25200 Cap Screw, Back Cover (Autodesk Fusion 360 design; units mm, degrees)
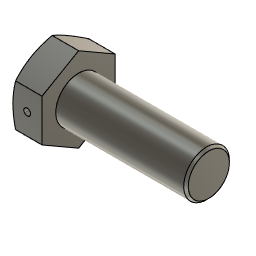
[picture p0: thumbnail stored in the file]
sketch "Main Profile" plane through (0, 0, 0) normal (0, 1, 0) x axis (1, 0, 0)
  line L1 (27.7812, 0) -> (0, 0)
  line L2 (27.7812, -3.9688) -> (27.7812, 0)
  line L3 (5.1594, -3.9687) -> (27.7812, -3.9688)
  line L4 (5.1594, -6.35) -> (5.1594, -3.9687)
  line L5 (0, -6.35) -> (5.1594, -6.35)
  line L6 (0, 0) -> (0, -6.35)
  point P1 (0, 0)
  point P2 (0, 0)
  point P8 (0, 0)
  point P4 (27.7812, -3.9688)
  point P5 (5.1594, -3.9687)
  point P6 (5.1594, -6.35)
  point P7 (0, -6.35)
  point P3 (27.7812, 0)
  coincident P1 P2
  horizontal L1
  perpendicular L1 L2
  perpendicular L2 L3
  perpendicular L3 L4
  perpendicular L4 L5
  coincident P1 P8
  vertical L6
  dimension "d1" distance P4 P5 = 22.6219
  dimension "d2" distance P6 P7 = 5.1594 (= "( 13 / 64 ) * 1 in")
  dimension "d3" distance P3 P4 = 3.9688 (= "( 0.3125 / 2 ) * 1 in")
  dimension "d4" distance P7 P8 = 6.35 (= "( 1 / 4 ) * 1 in")
revolve "Revolve1" sketch "Main Profile" AlongAngle 360 bodies "25200 Cap Screw, Back Cover"
sketch "Hex Profile" plane through (0, 0, 0) normal (-1, 0, 0) x axis (0, -1, 0)
  line L1 (-6.35, 3.6662) -> (0, 7.3323)
  line L2 (-6.35, -3.6662) -> (-6.35, 3.6662)
  line L3 (0, -7.3323) -> (-6.35, -3.6662)
  line L4 (6.35, -3.6662) -> (0, -7.3323)
  line L5 (6.35, 3.6662) -> (6.35, -3.6662)
  line L6 (0, 7.3323) -> (6.35, 3.6662)
  line L7 (0, 7.3323) -> (0, 0)
  circle C1 centre (0, 0) radius 6.35
  point P1 (0, 0)
  point P9 (0, 0)
  point P10 (0, 0)
  coincident P1 P9
  coincident P1 P10
  vertical L7
  dimension "d6" distance L2 L5 = 12.7 (= "( 1 / 2 ) * 1 in")
extrude "Extrude1" add sketch "Hex Profile" profile of C1 L1 L2 L3 L4 L5 L6 against normal blind 5.1594 (magnitude of "( -13 / 64 ) * 1 in")
chamfer "Chamfer1" distance 0.3969 (= "( 1 / 64 ) * 1 in")
sketch "Hex Cut Profile" plane through (0, 0, 0) normal (0, 1, 0) x axis (1, 0, 0)
  line L1 (0, -3.6662) -> (0, -7.3323)
  line L2 (5.1594, -3.6662) -> (0, -3.6662)
  line L3 (5.1594, -7.3323) -> (5.1594, -3.6662)
  line L4 (0, -7.3323) -> (5.1594, -7.3323)
  line L5 (0.5552, -7.3323) -> (0, -6.1417)
  point P7 (0.5552, -7.3323)
  point P6 (0, -6.1417)
  coincident L4 P7
  coincident L1 P6
  dimension "d10" angle L1 L5 = 25
  dimension "d11" distance P6 P7 = 1.1906 (= "( 3 / 64 ) * 1 in")
revolve "Revolve2" sketch "Hex Cut Profile" AlongAngle 360
sketch "Wire Seal Hole Profile" plane through (0, -6.35, 0) normal (0, -1, 0) x axis (1, 0, 0)
  curve K1 (0.5552, -3.6662) -> (0.5552, 3.6662)
  line L1 (5.1594, -3.6662) -> (0.5552, -3.6662)
  line L2 (5.1594, 3.6662) -> (5.1594, -3.6662)
  line L3 (0.5552, 3.6662) -> (5.1594, 3.6662)
  line L4 (5.1594, 0) -> (0, 0)
  circle C1 centre (2.5797, 0) radius 0.5953
  point P1 (0, 0)
  point P6 (0, 0)
  point P7 (5.1594, 0)
  point P8 (2.5797, 0)
  coincident P1 P6
  horizontal L4
  coincident L2 P7
  midpoint L4 P8
  dimension "d13" diameter C1 = 1.1906 (= "( 3 / 64 ) * 1 in")
extrude "Extrude2" cut sketch "Wire Seal Hole Profile" profile of C1 against normal blind 12.7
named bodies: "25200 Cap Screw, Back Cover"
